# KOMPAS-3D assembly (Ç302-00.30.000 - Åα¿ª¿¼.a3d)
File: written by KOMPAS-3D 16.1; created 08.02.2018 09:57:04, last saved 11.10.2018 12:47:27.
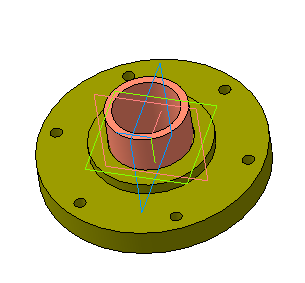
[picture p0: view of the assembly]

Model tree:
1. Эскиз:1
2. Вырезать элемент выдавливания:1
     Расстояние 1 = 5
3. Эскиз:2
4. Вырезать элемент вращения:1  (labels: Полипропилен  ГОСТ 26996-86)
     Угол 1 = 360

Referenced files in Z:\Мембранные насосы\Мембранный электропривод\А302-00.00.000 - ASTRA-302 (МЭ200)\3Д\: А302-00.30.001 - Прижим.m3d
Referenced files in Z:\1 ПКИ 3D\Полипропиленовые фитинги, трубы\: Труба ф40х3,7 (PN10) FV PPR ф. FV PLAST.m3d
Referenced files in Z:\Мембранные насосы\Мембранный электропривод\А302-00.00.000 - ASTRA-302 (МЭ200)\Чертежи\: А302-00.30.001 - Прижим.cdw
Referenced files: GRAPHIC.TDP
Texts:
  Полиамид П-12Б-20  ТУ 6-05-898-73
  Труба 40 PN10 S=3,7 FV PPR ф. FV PLAST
